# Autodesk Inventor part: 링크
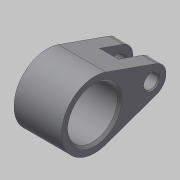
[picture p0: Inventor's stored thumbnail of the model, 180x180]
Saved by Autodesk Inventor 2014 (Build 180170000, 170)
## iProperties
Created: 2016-08
Part Number: 링크
Material: 강철, 탄소
Document SubType Name: Modeling
Designer: mduedu
Density: 7.87 g/cm^3
Appearance: Default
Author: mduedu
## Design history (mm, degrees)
sketch "스케치1"
  geometry: L1 (26, 5.657)-(4.667, 13.199); L2 (26, -5.657)-(4.667, -13.199); C1 r 10.5 at (0, 0); C2 r 3 at (24, 0); A1 r 14 centre (0, 0) between (4.667, 13.199) and (4.667, -13.199); A2 r 6 centre (24, 0) between (26, 5.657) and (26, -5.657); 1 further point
  constraints: 4 centre point, 4 end point, 4 point on circle, 4 tangent, 3 coincident, 1 horizontal alignment
  dimensions: "d0" = 28 diameter of A1; "d2" = 12 diameter of A2; "d3" = 24 distance of A2.centre point (0, 0); "d4" = 21 diameter of C1; "d5" = 6 diameter of C2
extrude "돌출1" new body sketch "스케치1" stored distance "d6" = 20; taper "d7" = 0 deg
sketch "스케치2"
  geometry: L1 (-10, 30)-(10, 30) reference; L2 (0, 0)-(0, 30); L3 (-4, 30)-(4, 30); L4 (4, 30)-(4, 16); L5 (4, 16)-(-4, 16); L6 (-4, 16)-(-4, 30)
  constraints: 10 end point, 2 midpoint, 2 parallel, 1 horizontal, 1 perpendicular, 1 point on line
  dimensions: "d8" = 8 distance between parallel lines of L4 L6; "d10" = 14 distance of L3.end L4.end
extrude "돌출2" cut sketch "스케치2" stored distance "d11" = 20; taper "d12" = 0 deg
chamfer "모따기1" distance "d13" = 1; stored, may be unused: second distance "d14" = 2, angle "d15" = 45 deg
chamfer "모따기2" distance "d16" = 0.5; stored, may be unused: second distance "d17" = 2, angle "d18" = 45 deg
node "솔리드1"
